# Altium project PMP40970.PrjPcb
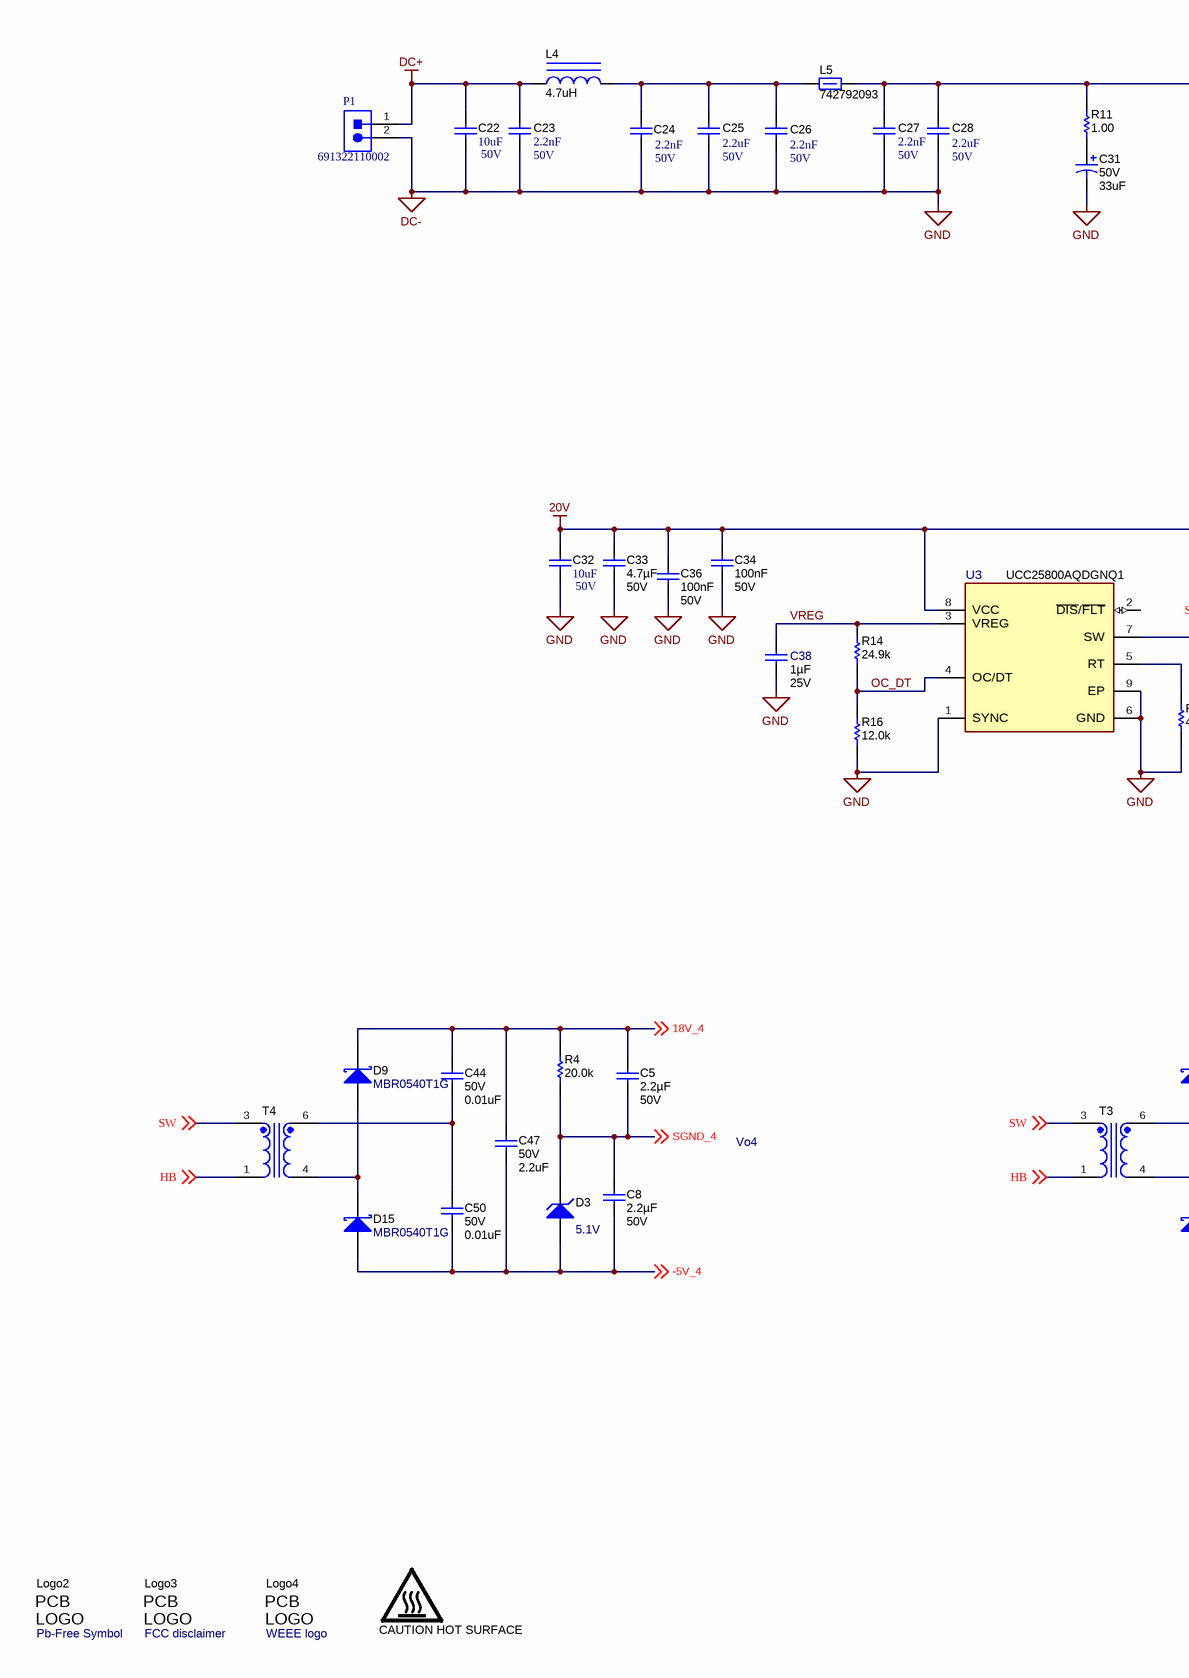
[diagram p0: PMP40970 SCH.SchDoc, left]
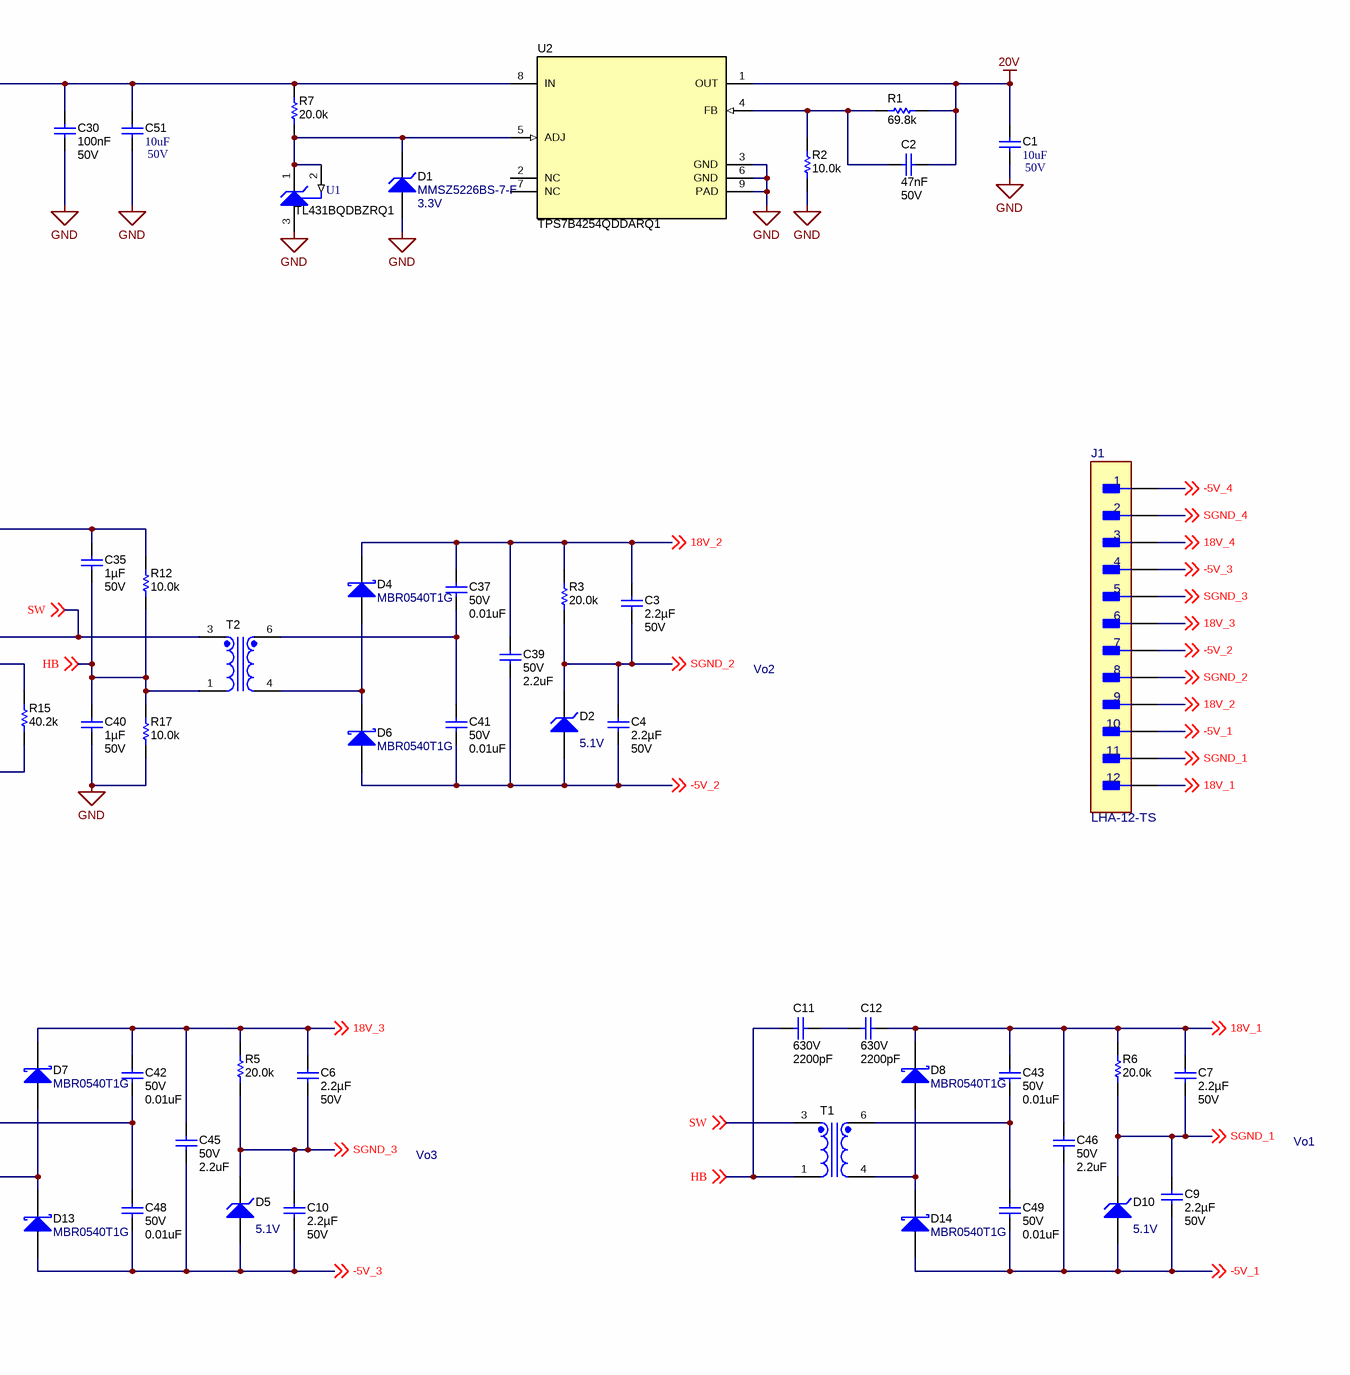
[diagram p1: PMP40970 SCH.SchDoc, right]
CopyrightYear: 2021; PCB_Rev: A; PRJ_Customer: Public Release; PRJ_Number: PMP40970; SCH_Rev: A; TechSupport: http://www.ti.com/support; TID: N/A
1 sheet, 82 parts. Net scope: global (net labels, ports and power ports of the same name join across sheets).
Board file: PMP40970 PCB.PcbDoc

## Sheet PMP40970 SCH.SchDoc
size A2; Date: Not shown in title block; ApprovedBy: Not shown in title block; CheckedBy: Not shown in title block; Author: Not shown in title block; CompanyName: Not shown in title block; Engineer: Not shown in title block; Organization: Not shown in title block; Address1: Not shown in title block; Address2: Not shown in title block; Address3: Not shown in title block; Address4: Not shown in title block; DocumentNumber: 1; Revision: Use project parameter SCH_Rev; SheetNumber: 1; SheetTotal: 1; PageSetup: Record=PageOptions¦CenterHorizontal=True¦CenterVertical=True¦PrintScale=1.00¦XCorrection=1.00¦YCorrection=1.00¦PrintKind=0¦BorderSize=5000000¦LeftOffset=0¦BottomOffset=0¦Orientation=2¦PaperLength=1000¦PaperWidth=1000¦Scale=100¦PaperSource=15¦PrintQuality=600¦MediaType=1¦DitherType=10¦PaperKind=Letter¦PrintScaleMode=1

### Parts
C1  VDC_V: 50V  ValueDisplayed: 10uF  [1210_280]  (hidden comment: UMK325AB7106KMHT)
C2  Cap_F: 47nF  VDC_V: 50V  [0603]  (hidden comment: CGA3E2X7R1H473K080AA)
C3  Cap_F: 2.2µF  VDC_V: 50V  [0805_HV]  (hidden comment: CGA4J3X7R1H225K125AE)
C4  Cap_F: 2.2µF  VDC_V: 50V  [0805_HV]  (hidden comment: CGA4J3X7R1H225K125AE)
C5  Cap_F: 2.2µF  VDC_V: 50V  [0805_HV]  (hidden comment: CGA4J3X7R1H225K125AE)
C6  Cap_F: 2.2µF  VDC_V: 50V  [0805_HV]  (hidden comment: CGA4J3X7R1H225K125AE)
C7  Cap_F: 2.2µF  VDC_V: 50V  [0805_HV]  (hidden comment: CGA4J3X7R1H225K125AE)
C8  Cap_F: 2.2µF  VDC_V: 50V  [0805_HV]  (hidden comment: CGA4J3X7R1H225K125AE)
C9  Cap_F: 2.2µF  VDC_V: 50V  [0805_HV]  (hidden comment: CGA4J3X7R1H225K125AE)
C10  Cap_F: 2.2µF  VDC_V: 50V  [0805_HV]  (hidden comment: CGA4J3X7R1H225K125AE)
C11  VDC_V: 630V  ValueDisplayed: 2200pF  [1206]  (hidden comment: GRM31BR72J222KW01L)
C12  VDC_V: 630V  ValueDisplayed: 2200pF  [1206]  (hidden comment: GRM31BR72J222KW01L)
C22  VDC_V: 50V  ValueDisplayed: 10uF  [1210_280]  (hidden comment: UMK325AB7106KMHT)
C23  Cap_F: 2.2nF  VDC_V: 50V  [0603]  (hidden comment: C0603C222K5RACTU)
C24  Cap_F: 2.2nF  VDC_V: 50V  [0603]  (hidden comment: C0603C222K5RACTU)
C25  VDC_V: 50V  ValueDisplayed: 2.2uF  [1206_180]  (hidden comment: GCM31CR71H225KA55L)
C26  Cap_F: 2.2nF  VDC_V: 50V  [0603]  (hidden comment: C0603C222K5RACTU)
C27  Cap_F: 2.2nF  VDC_V: 50V  [0603]  (hidden comment: C0603C222K5RACTU)
C28  VDC_V: 50V  ValueDisplayed: 2.2uF  [1206_180]  (hidden comment: GCM31CR71H225KA55L)
C30  Cap_F: 100nF  VDC_V: 50V  [0603]  (hidden comment: 06035C104KAZ2A)
C31  VDC_V: 50V  ValueDisplayed: 33uF  [SM_RADIAL_6.3BMM]  (hidden comment: EEHZC1H330XP)
C32  VDC_V: 50V  ValueDisplayed: 10uF  [1210_280]  (hidden comment: UMK325AB7106KMHT)
C33  ValueDisplayed: 4.7µF  VDC_V: 50V  [1206_190]  (hidden comment: CGA5L3X7R1H475K160AE)
C34  Cap_F: 100nF  VDC_V: 50V  [0603]  (hidden comment: 06035C104KAZ2A)
C35  Cap_F: 1µF  VDC_V: 50V  [0805_HV]  (hidden comment: CGA4J3X7R1H105K125AB)
C36  Cap_F: 100nF  VDC_V: 50V  [0603]  (hidden comment: 06035C104KAZ2A)
C37  VDC_V: 50V  ValueDisplayed: 0.01uF  [0603]  (hidden comment: CGA3E2C0G1H103J080AA)
C38  Cap_F: 1µF  VDC_V: 25V  [0603]  (hidden comment: CGA3E1X7R1E105K080AC)
C39  VDC_V: 50V  ValueDisplayed: 2.2uF  [1206_180]  (hidden comment: GCM31CR71H225KA55L)
C40  Cap_F: 1µF  VDC_V: 50V  [0805_HV]  (hidden comment: CGA4J3X7R1H105K125AB)
C41  VDC_V: 50V  ValueDisplayed: 0.01uF  [0603]  (hidden comment: CGA3E2C0G1H103J080AA)
C42  VDC_V: 50V  ValueDisplayed: 0.01uF  [0603]  (hidden comment: CGA3E2C0G1H103J080AA)
C43  VDC_V: 50V  ValueDisplayed: 0.01uF  [0603]  (hidden comment: CGA3E2C0G1H103J080AA)
C44  VDC_V: 50V  ValueDisplayed: 0.01uF  [0603]  (hidden comment: CGA3E2C0G1H103J080AA)
C45  VDC_V: 50V  ValueDisplayed: 2.2uF  [1206_180]  (hidden comment: GCM31CR71H225KA55L)
C46  VDC_V: 50V  ValueDisplayed: 2.2uF  [1206_180]  (hidden comment: GCM31CR71H225KA55L)
C47  VDC_V: 50V  ValueDisplayed: 2.2uF  [1206_180]  (hidden comment: GCM31CR71H225KA55L)
C48  VDC_V: 50V  ValueDisplayed: 0.01uF  [0603]  (hidden comment: CGA3E2C0G1H103J080AA)
C49  VDC_V: 50V  ValueDisplayed: 0.01uF  [0603]  (hidden comment: CGA3E2C0G1H103J080AA)
C50  VDC_V: 50V  ValueDisplayed: 0.01uF  [0603]  (hidden comment: CGA3E2C0G1H103J080AA)
C51  VDC_V: 50V  ValueDisplayed: 10uF  [1210_280]  (hidden comment: UMK325AB7106KMHT)
D1  MMSZ5226BS-7-F  value 3.3V  [SOD-323]
D2  value 5.1V  [SOD-323]  (hidden comment: BZT52C5V1S-7-F)
D3  value 5.1V  [SOD-323]  (hidden comment: BZT52C5V1S-7-F)
D4  MBR0540T1G  [SOD-123]
D5  value 5.1V  [SOD-323]  (hidden comment: BZT52C5V1S-7-F)
D6  MBR0540T1G  [SOD-123]
D7  MBR0540T1G  [SOD-123]
D8  MBR0540T1G  [SOD-123]
D9  MBR0540T1G  [SOD-123]
D10  value 5.1V  [SOD-323]  (hidden comment: BZT52C5V1S-7-F)
D13  MBR0540T1G  [SOD-123]
D14  MBR0540T1G  [SOD-123]
D15  MBR0540T1G  [SOD-123]
J1  LHA-12-TS  [FP-LHA-12-TS_HDR12-MFG]
L4  ValueDisplayed: 4.7uH  [XFL3010]  (hidden comment: XFL3010-472MEB)
L5  742792093  [0805_HV]
LOGO1  CAUTION HOT SURFACE  [IEC_HotSurface_Small]  (no BOM)
Logo2  Pb-Free Symbol  [Pb-Free_Overlay_Medium]  (no BOM)
Logo3  FCC disclaimer  [FCC_disclaimer]  (no BOM)
Logo4  WEEE logo  [WEEE_Minimum]  (no BOM)
P1  691322110002  [691322110002]
R1  ValueDisplayed: 69.8k  [0603]  (hidden comment: CRCW060369K8FKEA)
R2  ValueDisplayed: 10.0k  [0603]  (hidden comment: CRCW060310K0FKEA)
R3  ValueDisplayed: 20.0k  [0603]  (hidden comment: ERJ-3EKF2002V)
R4  ValueDisplayed: 20.0k  [0603]  (hidden comment: ERJ-3EKF2002V)
R5  ValueDisplayed: 20.0k  [0603]  (hidden comment: ERJ-3EKF2002V)
R6  ValueDisplayed: 20.0k  [0603]  (hidden comment: ERJ-3EKF2002V)
R7  ValueDisplayed: 20.0k  [0603]  (hidden comment: RC0603FR-0720KL)
R11  ValueDisplayed: 1.00  [0603]  (hidden comment: CRCW06031R00FKEA)
R12  ValueDisplayed: 10.0k  [0603]  (hidden comment: CRCW060310K0FKEA)
R14  ValueDisplayed: 24.9k  [0603]  (hidden comment: RC0603FR-0724K9L)
R15  ValueDisplayed: 40.2k  [0603]  (hidden comment: ERJ-3EKF4022V)
R16  ValueDisplayed: 12.0k  [0603]  (hidden comment: RC0603FR-0712KL)
R17  ValueDisplayed: 10.0k  [0603]  (hidden comment: CRCW060310K0FKEA)
T1  (no value)  [Wurth_WE-GDT_EP5]
T2  (no value)  [Wurth_WE-GDT_EP5]
T3  (no value)  [Wurth_WE-GDT_EP5]
T4  (no value)  [Wurth_WE-GDT_EP5]
U1  TL431BQDBZRQ1  [DBZ0003A_N]
U2  TPS7B4254QDDARQ1  [DDA0008J]
U3  UCC25800AQDGNQ1  [DGN0008G-MFG]

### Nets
20V: C1.1 C2.1 C32.1 C33.2 C34.1 C35.1 C36.1 R1.2 R12.2 U2.1(OUT) U3.8(VCC)
DC+: C22.1 C23.1 L4.1 P1.1
DC-: C1.2 C22.2 C23.2 C24.2 C25.2 C26.2 C27.2 C28.2 C30.2 C31.2(-) C32.2 C33.1 C34.2 C36.2 C38.2 C40.2 C51.2 D1.2(A) P1.2 R2.2 R15.1 R16.1 R17.1 U1.3(ANODE) U2.3(GND) U2.6(GND) U2.9(PAD) U3.1(SYNC) U3.6(GND) U3.9(EP)  [also labelled GND]
18V_1: C7.1 C12.1 C43.1 C46.1 D8.1(K) J1.12 R6.2 ; off-sheet 18V_1
18V_2: C3.1 C37.1 C39.1 D4.1(K) J1.9 R3.2 ; off-sheet 18V_2
18V_3: C6.1 C42.1 C45.1 D7.1(K) J1.6 R5.2 ; off-sheet 18V_3
18V_4: C5.1 C44.1 C47.1 D9.1(K) J1.3 R4.2 ; off-sheet 18V_4
-5V_1: C9.2 C46.2 C49.2 D10.2(A) D14.2(A) J1.10 ; off-sheet -5V_1
-5V_2: C4.2 C39.2 C41.2 D2.2(A) D6.2(A) J1.7 ; off-sheet -5V_2
-5V_3: C10.2 C45.2 C48.2 D5.2(A) D13.2(A) J1.4 ; off-sheet -5V_3
-5V_4: C8.2 C47.2 C50.2 D3.2(A) D15.2(A) J1.1 ; off-sheet -5V_4
HB: C11.2 C35.2 C40.1 R12.1 R17.2 T1.1 T2.1 T3.1 T4.1 ; off-sheet HB
OC_DT: R14.1 R16.2 U3.4(OC/DT)
SGND_1: C7.2 C9.1 D10.1(K) J1.11 R6.1 ; off-sheet SGND_1
SGND_2: C3.2 C4.1 D2.1(K) J1.8 R3.1 ; off-sheet SGND_2
SGND_3: C6.2 C10.1 D5.1(K) J1.5 R5.1 ; off-sheet SGND_3
SGND_4: C5.2 C8.1 D3.1(K) J1.2 R4.1 ; off-sheet SGND_4
SW: T1.3 T2.3 T3.3 T4.3 U3.7(SW) ; off-sheet SW
VREG: C38.1 R14.2 U3.3(VREG)
NetC2_2: C2.2 R1.1 R2.1 U2.4(FB)
NetC11_1: C11.1 C12.2
NetC24_1: C24.1 C25.1 C26.1 L4.2 L5.1
NetC27_1: C27.1 C28.1 C30.1 C51.1 L5.2 R7.2 R11.2 U2.8(IN)
NetC31_1: C31.1(+) R11.1
NetC37_2: C37.2 C41.1 T2.6
NetC42_2: C42.2 C48.1 T3.6
NetC43_2: C43.2 C49.1 T1.6
NetC44_2: C44.2 C50.1 T4.6
NetD1_1: D1.1(K) R7.1 U1.1(CATHODE) U1.2(REF) U2.5(ADJ)
NetD4_2: D4.2(A) D6.1(K) T2.4
NetD7_2: D7.2(A) D13.1(K) T3.4
NetD8_2: D8.2(A) D14.1(K) T1.4
NetD9_2: D9.2(A) D15.1(K) T4.4
NetR15_2: R15.2 U3.5(RT)

Not connected (* = marked no-connect by the designer): U2 2(NC) 7(NC); U3 2(~{DIS}/~{FLT})

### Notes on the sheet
- Vo2
- Vo4
- Vo1
- Vo3

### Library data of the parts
C1 C22 C32 C51 = CMP-0009258-2: CAP, CERM, 10 uF, 50 V, +/- 10%, X7R, AEC-Q200 Grade 1, 1210; Manufacturer: Taiyo Yuden; TaMin_C: -55°C; Polarized: N; SizeAreaWB_mm2: 14.7; Value1: Unknown; U/M: EA; Value: 10uF; TaMax_C: 125°C; SizeZ_mm: 2.8; SizeX_mm: 3.2; SizeY_mm: 2.5; Cap_Case: 1210; SizeArea_mm2: 8; AEC Qualified: Y; Cap_F: 10µF; AEC Grade: 1; AEC Category: Q200
C2 = CMP-0007079-2: CAP, CERM, 0.047 uF, 50 V, +/- 10%, X7R, AEC-Q200 Grade 1, 0603; Manufacturer: TDK; TaMin_C: -55°C; ESR_ohm: 0.049007; Polarized: N; SizeAreaWB_mm2: 4.68; Value1: 0.049007 ohm; U/M: EA; TaMax_C: 125°C; SizeZ_mm: 1; SizeX_mm: 1.6; SizeY_mm: 0.8; SizeArea_mm2: 1.28; AEC Qualified: Y; IRMS_A: 767.528mA; AEC Category: Q200
C3-C10 = CMP-0860897-1: CAP, CERM, 2.2 µF, 50 V,+/- 10%, X7R, AEC-Q200 Grade 1, 0805; Manufacturer: TDK; SizeAreaWB_mm2: 6.75; U/M: EA; TaMin_C: -55°C; Cap_Case: 0805; Value: 2.2uF; AEC Category: Q200; SizeArea_mm2: 2.5; SizeY_mm: 1.25; Polarized: N; AEC Grade: 1; SizeZ_mm: 1.45; AEC Qualified: Y; TaMax_C: 125°C; SizeX_mm: 2
C11 C12 = CMP-0008912-1: CAP, CERM, 2200 pF, 630 V, +/- 10%, X7R, 1206; Manufacturer: MuRata; TaMin_C: -55°C; Polarized: N; SizeAreaWB_mm2: 10.92; Value1: Unknown; U/M: EA; Value: 2200pF; TaMax_C: 125°C; SizeZ_mm: 1.35; SizeX_mm: 3.2; SizeY_mm: 1.6; SizeArea_mm2: 5.12; Cap_F: 2.2nF; AEC Category: Q200
C23 C24 C26 C27 = CMP-0006898-4: CAP, CERM, 2200 pF, 50 V, +/- 10%, X7R, 0603; Manufacturer: Kemet; TaMin_C: -55°C; Polarized: N; SizeAreaWB_mm2: 4.68; Value1: Unknown; U/M: EA; Value: 2200pF; TaMax_C: 125°C; SizeZ_mm: 1; SizeX_mm: 1.6; SizeY_mm: 0.8; SizeArea_mm2: 1.28; AEC Category: Q200
C25 C28 = CMP-0008814-2: CAP, CERM, 2.2 uF, 50 V, +/- 10%, X7R, AEC-Q200 Grade 1, 1206; Manufacturer: MuRata; TaMin_C: -55°C; Polarized: N; SizeAreaWB_mm2: 10.92; Value1: Unknown; U/M: EA; Value: 2.2uF; TaMax_C: 125°C; SizeZ_mm: 1.8; SizeX_mm: 3.2; SizeY_mm: 1.6; Cap_Case: 1206; SizeArea_mm2: 5.12; AEC Qualified: Y; Cap_F: 2.2µF; AEC Grade: 1; AEC Category: Q200
C30 C34 C36 = CMP-0079095-1: CAP, CERM, 0.1 µF, 50 V,+/- 10%, X7R, AEC-Q200 Grade 1, 0603; Manufacturer: AVX; SizeAreaWB_mm2: 4.68; SizeArea_mm2: 1.28; AEC Qualified: Y; AEC Category: Q200; Value: 0.1uF; TaMax_C: 125°C; SizeZ_mm: 1; Polarized: N; TaMin_C: -55°C; SizeY_mm: 0.8; U/M: EA; SizeX_mm: 1.6; ValueDisplayed: 0.1µF
C31 = CMP-0012598-3: CAP, Polymer Hybrid, 33 uF, 50 V, +/- 20%, 40 ohm, 6.3x7.7 SMD; Manufacturer: Panasonic; TaMin_C: -55°C; ESR_ohm: 40; Polarized: Y; SizeAreaWB_mm2: 79.98; Value1: 40 ohm; Value: 33uF; TaMax_C: 125°C; SizeZ_mm: 7.7; SizeX_mm: 7.3; SizeY_mm: 6.6; SizeArea_mm2: 48.18; CompType: Capacitor; Cap_F: 33µF; IRMS_A: 1.1A; AEC Category: Q200
C33 = CMP-0085349-1: CAP, CERM, 4.7 µF, 50 V,+/- 10%, X7R, AEC-Q200 Grade 1, 1206; Manufacturer: TDK; Cap_Case: 1206; AEC Category: Q200; SizeY_mm: 1.6; TaMin_C: -55°C; TaMax_C: 125°C; U/M: EA; AEC Qualified: Y; SizeAreaWB_mm2: 10.92; AEC Grade: 1; SizeZ_mm: 1.9; SizeArea_mm2: 5.12; Value: 4.7uF; Polarized: N; SizeX_mm: 3.2
C35 C40 = CMP-0007976-2: CAP, CERM, 1 uF, 50 V, +/- 10%, X7R, AEC-Q200 Grade 1, 0805; Manufacturer: TDK; TaMin_C: -55°C; ESR_ohm: 8.782m; Polarized: N; SizeAreaWB_mm2: 6.75; Value1: 0.008782 ohm; U/M: EA; Value: 1uF; TaMax_C: 125°C; SizeZ_mm: 1.45; SizeX_mm: 2; SizeY_mm: 1.25; Cap_Case: 0805; SizeArea_mm2: 2.5; AEC Qualified: Y; IRMS_A: 2.20488A; AEC Grade: 1; AEC Category: Q200
C37 C41-C44 C48-C50 = CMP-0007070-3: CAP, CERM, 0.01 uF, 50 V, +/- 5%, C0G/NP0, AEC-Q200 Grade 1, 0603; Manufacturer: TDK; TaMin_C: -55°C; Polarized: N; SizeAreaWB_mm2: 4.68; Value1: Unknown; U/M: EA; Value: 0.01uF; TaMax_C: 125°C; SizeZ_mm: 1; SizeX_mm: 1.6; SizeY_mm: 0.8; SizeArea_mm2: 1.28; AEC Qualified: Y; Cap_F: 10nF; AEC Category: Q200
C38 = CMP-0076705-3: CAP, CERM, 1 µF, 25 V,+/- 10%, X7R, AEC-Q200 Grade 1, 0603; Manufacturer: TDK; SizeAreaWB_mm2: 4.68; SizeArea_mm2: 1.28; AEC Qualified: Y; AEC Category: Q200; Value: 1uF; TaMax_C: 125°C; SizeZ_mm: 1.0; AEC Grade: 1; Polarized: N; TaMin_C: -55°C; SizeY_mm: 0.8; U/M: EA; SizeX_mm: 1.6; Cap_Case: 1.6x0.8x0.8mm
C39 C45-C47 = CMP-0008814-1: CAP, CERM, 2.2 uF, 50 V, +/- 10%, X7R, AEC-Q200 Grade 1, 1206; Manufacturer: MuRata; TaMin_C: -55°C; Polarized: N; SizeAreaWB_mm2: 10.92; Value1: Unknown; U/M: EA; Value: 2.2uF; TaMax_C: 125°C; SizeZ_mm: 1.8; SizeX_mm: 3.2; SizeY_mm: 1.6; Cap_Case: 1206; SizeArea_mm2: 5.12; AEC Qualified: Y; Cap_F: 2.2µF; AEC Grade: 1; AEC Category: Q200
D1 = CMP-0005849-3: Diode, Zener, 3.3 V, 200 mW, SOD-323; Manufacturer: Diodes Inc.; SizeArea_mm2: 3.645; SizeY_mm: 1.35; RJA_CperW: 350; AEC Category: Q101; Value1: 0.2W; SizeX_mm: 2.7; SizeAreaWB_mm2: 8.695; SizeZ_mm: 1; Power_W: 200mW
D2 D3 D5 D10 = CMP-0005865-2: Diode, Zener, 5.1 V, 200 mW, SOD-323; Manufacturer: Diodes Inc.; SizeY_mm: 1.35; SizeZ_mm: 1; AEC Category: Q101; Power_W: 200mW; SizeX_mm: 2.7; SizeAreaWB_mm2: 8.695; RJA_CperW: 625; SizeArea_mm2: 3.645; Value1: 0.2W
D4 D6-D9 D13-D15 = CMP-0028526-1: Diode, Schottky, 40 V, 0.5 A, SOD-123; Manufacturer: ON Semiconductor; Io_A: 500mA; Green_Lifecycle: Active; SizeAreaWB_mm2: 13.095; Vr_V: 40V; Green_REACh: Passed; Value1: 0.5A; TJmax_C: 150°C; U/M: EA; Value: 40V; SizeZ_mm: 1.35; SizeX_mm: 3.85; SizeY_mm: 1.7; Vf_V: 510mV; Value2: 0.51V; SizeArea_mm2: 6.545; AEC Category: Q101; RJC_CperW: 118
J1 = CMP-0089369-1: Manufacturer: Adam Tech; Conn Orientation: Straight; Conn Gender: Male; Voltage_V: 250V; Row_Count: 1; SizeZ_mm: 0.468inch; Current_A: 3A; ContactFinish: Tin,Copper; DUT-Pitch_mm: 2.54mm; AEC Qualified: No
L4 = CMP-0061132-1: Inductor, Shielded, Composite, 4.7 uH, 1.1 A, 0.22 ohm, SMD; Manufacturer: Coilcraft; Isat: 1.1A @ 30% inductance drop; Irms: 1.1A @ 40C rise; Green_Lifecycle: Not Set; SizeAreaWB_mm2: 16; DCR_ohm: 0.22; Green_REACh: Incomplete; Value: 4.7uH; Imax_A: 1.1A; SizeZ_mm: 1; SizeX_mm: 3; SizeArea_mm2: 9; Ind_H: 4.7µH; AEC Category: Q200
L5 = CMP-0003101-1: Ferrite Bead, 2200 ohm @ 100 MHz, 0.2 A, 0805; Manufacturer: Wurth Elektronik; Ztyp@1GHz_Ohm: 184.689; ZTyp@100MHz_Ohm: 2.2k; SizeAreaWB_mm2: 6.75; DCR_ohm: 0.6; Value1: 0.6 ohm; Imax_A: 200mA; SizeZ_mm: 1.45; SizeX_mm: 2; SizeY_mm: 1.25; Value2: 0.2A; SizeArea_mm2: 2.5
LOGO1 = CMP-0074837-1: IEC 61010-1 Hot Surface Warning; Library Reference: IEC_HotSurface; SymbolCreator: a0412235
Logo2 = CMP-0074839-1: SymbolCreator: a0412235
Logo3 = CMP-0074847-1: FCC_disclaimer
Logo4 = CMP-0074769-1
P1 = 691322110002: WR-TBL Serie 3221 Horizontal PCB Header, Pluggable, THT, pitch 3.5mm, 2p; Manufacturer: Wurth Elektronik; Modularity: No; Pin Number: 2; Rated Current [UL]: 10A; Working Voltage [UL]: 300VAC
R1 = CMP-0022556-2: RES, 69.8 k, 1%, 0.1 W, 0603; Manufacturer: Vishay-Dale; Power_W: 100mW; TempCo: 100 ppm/C; Value_Code: 69k8; U/M: EA; Value: 69.8k; EIA_Code: E96; SizeX_mm: 1.6; SizeY_mm: 0.8; SizeZ_mm: 1; Value2: 0.1W; SizeArea_mm2: 1.28; VDC_V: 75V; AEC Category: Q200
R2 R12 R17 = CMP-0021998-4: RES, 10.0 k, 1%, 0.1 W, AEC-Q200 Grade 0, 0603; Manufacturer: Vishay-Dale; Power_W: 100mW; TempCo: 100 ppm/C; Value_Code: 10k0; Value: 10.0k; EIA_Code: E96; Res_ohm: 10k; SizeX_mm: 1.6; SizeY_mm: 0.8; SizeZ_mm: 1; Value2: 0.1W; SizeArea_mm2: 1.28; AEC Qualified: Y; VDC_V: 75V; AEC Category: Q200; AEC Grade: 0
R3-R6 = CMP-0022691-1: RES, 20.0 k, 1%, 0.1 W, AEC-Q200 Grade 0, 0603; Manufacturer: Panasonic; Power_W: 100mW; TempCo: 100 ppm/C; Value_Code: 20k0; U/M: EA; Value: 20.0k; Res_ohm: 20k; SizeX_mm: 1.6; SizeY_mm: 0.8; SizeZ_mm: 1; Value2: 0.1W; SizeArea_mm2: 1.28; AEC Qualified: Y; VDC_V: 75V; AEC Grade: 0; AEC Category: Q200; EIA_Code: E96
R7 = CMP-0022906-4: RES, 20.0 k, 1%, 0.1 W, 0603; Manufacturer: Yageo America; Power_W: 100mW; TempCo: 100 ppm/C; Value_Code: 20k0; Value: 20.0k; EIA_Code: E96; Res_ohm: 20k; SizeX_mm: 1.6; SizeY_mm: 0.8; SizeZ_mm: 1; Value2: 0.1W; SizeArea_mm2: 1.28; AEC Qualified: N; VDC_V: 75V; AEC Category: Q200; SizeAreaWB_mm2: 4.68
R11 = CMP-0022170-2: RES, 1.00, 1%, 0.1 W, 0603; Manufacturer: Vishay-Dale; Power_W: 100mW; TempCo: 100 ppm/C; Value_Code: 1R00; U/M: EA; Value: 1.00; EIA_Code: E96; Res_ohm: 1; SizeX_mm: 1.6; SizeY_mm: 0.8; Value2: 0.1W; SizeArea_mm2: 1.28; VDC_V: 75V; AEC Category: Q200
R14 = CMP-0022944-4: RES, 24.9 k, 1%, 0.1 W, 0603; Manufacturer: Yageo America; Power_W: 100mW; TempCo: 100 ppm/C; Value_Code: 24k9; Value: 24.9k; EIA_Code: E96; SizeX_mm: 1.6; SizeY_mm: 0.8; SizeZ_mm: 1; Value2: 0.1W; SizeArea_mm2: 1.28; AEC Qualified: N; VDC_V: 75V; AEC Category: Q200; SizeAreaWB_mm2: 4.68
R15 = CMP-0022700-1: RES, 40.2 k, 1%, 0.1 W, AEC-Q200 Grade 0, 0603; Manufacturer: Panasonic; Power_W: 100mW; TempCo: 100 ppm/C; Value_Code: 40k2; U/M: EA; Value: 40.2k; EIA_Code: E96; SizeX_mm: 1.6; SizeY_mm: 0.8; SizeZ_mm: 1; Value2: 0.1W; SizeArea_mm2: 1.28; AEC Qualified: Y; VDC_V: 75V; AEC Grade: 0; AEC Category: Q200
R16 = CMP-0022779-4: RES, 12.0 k, 1%, 0.1 W, 0603; Manufacturer: Yageo America; Power_W: 100mW; TempCo: 100 ppm/C; Value_Code: 12k0; Value: 12.0k; Res_ohm: 12k; SizeX_mm: 1.6; SizeY_mm: 0.8; SizeZ_mm: 1; Value2: 0.1W; SizeArea_mm2: 1.28; AEC Qualified: N; VDC_V: 75V; AEC Category: Q200; SizeAreaWB_mm2: 4.68
T1-T4 = CMP-0030729-1: Transformer; Manufacturer: Wurth Elektronik; PartNumber: 750345052; LeakageInd_H: 5.5µH; DCR_ohm: 1.2; Value: 650uH; Ind_H: 650µH
U1 = CMP-0032986-1: Automotive Catalog Adjustable Precision Shunt Regulator, 34 ppm / degC, 100 mA, -40 to 125 degC, 3-pin SOT-23 (DBZ), Green (RoHS & no Sb/Br); Manufacturer: Texas Instruments; VO Adj(Max)(V): 36; Temp Coeff(Typ)(ppm/ degree C): 34; SubFamily: Shunt Voltage Reference; Min Iz for Regulation(uA): 600; VO Adj(Min)(V): 2.495; Iout/Iz(Max)(mA): 100; Initial Accuracy @ 25/deg C(%): 0.5
U2 = CMP-0073874-1: 150-mA 40-V Voltage-Tracking LDO With 4-mV Tracking Tolerance, DDA0008J (SOIC-8); Alternate Manufacturer: Texas Instruments; Green_Lifecycle: Active; SizeAreaWB_mm2: 55.0511; Green_REACh: Passed; U/M: EA; SizeZ_mm: 1.7; SizeX_mm: 5.99; SizeY_mm: 4.89; SizeArea_mm2: 29.2911; CompType: IC
U3 = CMP-0088494-2: Open Loop LLC Transformer Driver for Isolated Bias Supplies; Manufacturer: Texas Instruments; Min Supply Voltage: 12V; SizeZ_mm: 1.1mm; Number Of Outputs: 1; Standoff Height: 0.05mm; AEC Category: Q200; Max Duty Cycle: 50%; TaMin_C: -40°C; TJmax_C: +150°C; AEC Qualified: No; Switching Frequency: 100-2000kHz; CompType: IC; Max Supply Voltage: 36V; TaMax_C: +125°C; Output Type: Other; Nominal Supply Current: 500uA

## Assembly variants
001: not fitted C31 C33 C51 D1 R11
